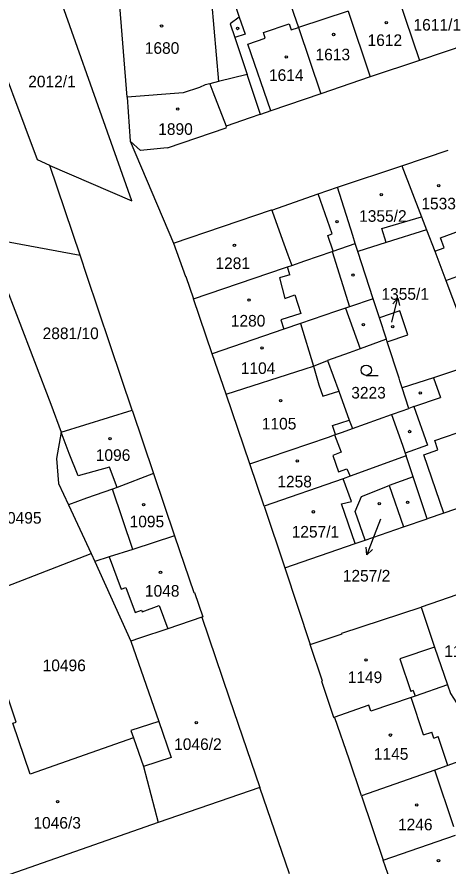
# Model space of a CAD drawing. Extents: x -564952 to -564307, y -1202373 to -1201847.
# Drawn here: x -564475.9 to -564412.8, y -1202215.7 to -1202091.3 of the extents above; entities that cross this region are included whole.
import ezdxf

# ---------------------------------------------------------------- set-up
doc = ezdxf.new("R2010")
doc.units = 0
for name, color, linetype in [('Hranice parcel', 7, 'Continuous'), ('Parcelní čísla', 7, 'Continuous'), ('Pop  PČ popisy', 7, 'Continuous'), ('Vnitřní kresba', 7, 'Continuous'), ('Značky budov', 7, 'Continuous'), ('Značky kultur', 7, 'Continuous')]:
    doc.layers.add(name, color=color, linetype=linetype)

msp = doc.modelspace()

# ---------------------------------------------------------------- linework, layer by layer
at = {"layer": 'Hranice parcel'}
for p, q in [((-564459.79, -1202103), (-564461.05, -1202087.35)), ((-564420.25, -1202088.03), (-564416.99, -1202097.64)), ((-564427.46, -1202090.41), (-564424.23, -1202100.06)), ((-564434.73, -1202092.8), (-564431.46, -1202102.52)), ((-564409.17, -1202094.97), (-564416.99, -1202097.64)), ((-564416.99, -1202097.64), (-564424.23, -1202100.06)), ((-564424.23, -1202100.06), (-564431.46, -1202102.52)), ((-564459.79, -1202103), (-564459.35, -1202109.45)), ((-564459.35, -1202109.45), (-564453, -1202124.38)), ((-564419.59, -1202113.07), (-564412.8, -1202110.76)), ((-564466.68, -1202126.15), (-564471.12, -1202112.99)), ((-564428.98, -1202116.19), (-564419.59, -1202113.07)), ((-564419.59, -1202113.07), (-564416.72, -1202120.54)), ((-564416.72, -1202120.54), (-564415.98, -1202122.44)), ((-564415.98, -1202122.44), (-564414.78, -1202125.53)), ((-564484.26, -1202122.87), (-564466.68, -1202126.15)), ((-564426.01, -1202125.59), (-564426.4, -1202124.41)), ((-564423.77, -1202132.5), (-564426.01, -1202125.59)), ((-564414.78, -1202125.53), (-564413.14, -1202129.85)), ((-564413.14, -1202129.85), (-564406.69, -1202127.47)), ((-564413.14, -1202129.85), (-564411.2, -1202134.99)), ((-564447.33, -1202140.55), (-564450.07, -1202132.51)), ((-564445.31, -1202146.49), (-564447.33, -1202140.55)), ((-564432.52, -1202142.36), (-564430.47, -1202141.57)), ((-564441.84, -1202156.68), (-564445.31, -1202146.49)), ((-564470.96, -1202147.96), (-564469.44, -1202152.01)), ((-564469.44, -1202152.01), (-564459.05, -1202148.8)), ((-564459.05, -1202148.8), (-564455.92, -1202158.1)), ((-564426.82, -1202151.52), (-564421.12, -1202149.47)), ((-564421.12, -1202149.47), (-564419.5, -1202153.95)), ((-564439.72, -1202162.87), (-564441.84, -1202156.68)), ((-564455.92, -1202158.1), (-564452.85, -1202167.22)), ((-564421.42, -1202159.82), (-564419.33, -1202165.89)), ((-564468.39, -1202162.66), (-564465.07, -1202169.78)), ((-564439.72, -1202162.87), (-564436.73, -1202171.88)), ((-564424.96, -1202167.83), (-564426.41, -1202163.62)), ((-564419.33, -1202165.89), (-564415.88, -1202164.71)), ((-564424.96, -1202167.83), (-564419.33, -1202165.89)), ((-564465.07, -1202169.78), (-564464.51, -1202170.97)), ((-564464.51, -1202170.97), (-564459.23, -1202182.61)), ((-564436.73, -1202171.88), (-564433, -1202183.12)), ((-564410.14, -1202175.34), (-564416.78, -1202177.62)), ((-564440.39, -1202204.01), (-564455.26, -1202209.13)), ((-564436.03, -1202216.65), (-564440.39, -1202204.01)), ((-564425.49, -1202205.25), (-564422.31, -1202214.68)), ((-564455.26, -1202209.13), (-564481.73, -1202218.41)), ((-564422.31, -1202214.68), (-564411.73, -1202210.99)), ((-564419.91, -1202221.63), (-564422.31, -1202214.68))]:
    msp.add_line(p, q, dxfattribs=at)
for points in [[(-564471.12, -1202112.99), (-564472.91, -1202112.19), (-564480.33, -1202092.49), (-564473.1, -1202078.61)], [(-564471.12, -1202112.99), (-564459.11, -1202118.17), (-564473.1, -1202078.61)], [(-564438.3, -1202082.34), (-564437.33, -1202085.18), (-564435.44, -1202090.73), (-564434.73, -1202092.8)], [(-564444.37, -1202088.37), (-564443.39, -1202091.32), (-564444.71, -1202092.27)], [(-564444.71, -1202092.27), (-564444.03, -1202094.3), (-564442.23, -1202099.7)], [(-564442.23, -1202099.7), (-564446.4, -1202100.73), (-564447.69, -1202101.05), (-564448.37, -1202101.22)], [(-564440.28, -1202105.54), (-564440.37, -1202105.26), (-564442.23, -1202099.7)], [(-564448.37, -1202101.22), (-564449.2, -1202101.6), (-564451.6, -1202102.39), (-564459.79, -1202103)], [(-564431.46, -1202102.52), (-564438.77, -1202105.01), (-564440.28, -1202105.54)], [(-564440.28, -1202105.54), (-564440.39, -1202105.56), (-564441.79, -1202106.04), (-564445.32, -1202107.24), (-564445.37, -1202107.57), (-564453.91, -1202110.48), (-564453.95, -1202110.41), (-564457.83, -1202110.82), (-564459.35, -1202109.45)], [(-564438.62, -1202119.56), (-564431.81, -1202117.18), (-564428.98, -1202116.19)], [(-564426.4, -1202124.41), (-564426.76, -1202123.25), (-564428.98, -1202116.19)], [(-564453, -1202124.38), (-564438.65, -1202119.52), (-564438.62, -1202119.56)], [(-564415.98, -1202122.44), (-564421.88, -1202124.29), (-564426.01, -1202125.59)], [(-564484.26, -1202122.87), (-564477.85, -1202129.99), (-564475.76, -1202135.44), (-564470.96, -1202147.96)], [(-564453, -1202124.38), (-564451.24, -1202129.27), (-564451.18, -1202129.25), (-564450.07, -1202132.51)], [(-564450.07, -1202132.51), (-564436.76, -1202128), (-564436.34, -1202127.85), (-564435.71, -1202127.63), (-564433.79, -1202126.97), (-564429.79, -1202125.58), (-564429.65, -1202125.53), (-564426.4, -1202124.41)], [(-564459.05, -1202148.8), (-564462.21, -1202139.4), (-564464.03, -1202134.02), (-564465.63, -1202129.27), (-564466.68, -1202126.15)], [(-564423.77, -1202132.5), (-564427.25, -1202133.68), (-564427.85, -1202133.89), (-564429.28, -1202134.37)], [(-564421.85, -1202138.41), (-564422.86, -1202135.31), (-564423.77, -1202132.5)], [(-564429.28, -1202134.37), (-564434.43, -1202136.12), (-564436.85, -1202136.95), (-564447.33, -1202140.55)], [(-564421.85, -1202138.41), (-564421.99, -1202138.46), (-564425.69, -1202139.82), (-564427.28, -1202140.4), (-564430.47, -1202141.57)], [(-564419.97, -1202144.14), (-564421.72, -1202138.83), (-564421.85, -1202138.41)], [(-564445.31, -1202146.49), (-564433.74, -1202142.77), (-564432.52, -1202142.36)], [(-564430.47, -1202141.57), (-564428.83, -1202146.03), (-564427.28, -1202150.27), (-564426.82, -1202151.52)], [(-564408.53, -1202141.96), (-564414.93, -1202144.06), (-564419.54, -1202145.57)], [(-564419.54, -1202145.57), (-564419.89, -1202144.52), (-564419.97, -1202144.14)], [(-564421.12, -1202149.47), (-564420.8, -1202149.35), (-564418.56, -1202148.56), (-564419.54, -1202145.57)], [(-564469.44, -1202152.01), (-564470.14, -1202155.87), (-564469.82, -1202159.55), (-564468.39, -1202162.66)], [(-564429.43, -1202152.44), (-564429.29, -1202152.39), (-564428.29, -1202152.02), (-564426.82, -1202151.52)], [(-564441.84, -1202156.68), (-564430.33, -1202152.75), (-564429.43, -1202152.44)], [(-564419.5, -1202153.95), (-564419.08, -1202155.11), (-564418.94, -1202155.51)], [(-564418.94, -1202155.51), (-564427.16, -1202158.47), (-564428.17, -1202158.84), (-564439.72, -1202162.87)], [(-564415.88, -1202164.71), (-564415.98, -1202164.41), (-564417.92, -1202158.58), (-564418.94, -1202155.51)], [(-564455.92, -1202158.1), (-564461.27, -1202160.11), (-564461.93, -1202160.36), (-564465.74, -1202161.69), (-564468.39, -1202162.66)], [(-564426.41, -1202163.62), (-564425.49, -1202161.44), (-564421.42, -1202159.82)], [(-564401.92, -1202159.96), (-564406.89, -1202161.65), (-564413.42, -1202163.87), (-564415.88, -1202164.71)], [(-564452.85, -1202167.22), (-564458.96, -1202169.19), (-564462.42, -1202170.3), (-564464.51, -1202170.97)], [(-564452.85, -1202167.22), (-564450.05, -1202175.52), (-564449.91, -1202175.48), (-564448.7, -1202179.07), (-564448.84, -1202179.12)], [(-564436.73, -1202171.88), (-564426.42, -1202168.33), (-564424.96, -1202167.83)], [(-564500.99, -1202168.69), (-564489.98, -1202179.46), (-564465.07, -1202169.78)], [(-564433, -1202183.12), (-564428.32, -1202181.55), (-564428.35, -1202181.47), (-564416.78, -1202177.62)], [(-564416.78, -1202177.62), (-564414.79, -1202183.49), (-564412.92, -1202189.01)], [(-564458.87, -1202196.74), (-564473.97, -1202202.06), (-564476.51, -1202194.63), (-564476.01, -1202194.45), (-564477.42, -1202190.36), (-564477.98, -1202190.57), (-564482.07, -1202179.28), (-564486.31, -1202180.92), (-564486.99, -1202179.15), (-564492.02, -1202181.09), (-564491.34, -1202182.86), (-564493.63, -1202183.74), (-564494.46, -1202184.06)], [(-564448.84, -1202179.12), (-564453.85, -1202180.8), (-564457.98, -1202182.19), (-564459.23, -1202182.61)], [(-564448.84, -1202179.12), (-564444.86, -1202190.93), (-564440.39, -1202204.01)], [(-564459.23, -1202182.61), (-564455.17, -1202194.39), (-564459.23, -1202195.69), (-564458.87, -1202196.74)], [(-564429.54, -1202193.79), (-564431.31, -1202188.54), (-564431.18, -1202188.49), (-564433, -1202183.12)], [(-564412.92, -1202189.01), (-564417.66, -1202190.65), (-564418.23, -1202190.85), (-564424.11, -1202192.88), (-564424.43, -1202191.99), (-564429.54, -1202193.79)], [(-564412.92, -1202189.01), (-564412.48, -1202190.3), (-564410.26, -1202193.68), (-564408.45, -1202199.22)], [(-564425.49, -1202205.25), (-564427.31, -1202199.89), (-564429.37, -1202193.82), (-564429.51, -1202193.87), (-564429.54, -1202193.79)], [(-564458.87, -1202196.74), (-564457.4, -1202200.98), (-564455.26, -1202209.13)], [(-564409.94, -1202199.76), (-564412.86, -1202200.81), (-564413, -1202200.86), (-564414.77, -1202201.48), (-564425.49, -1202205.25)]]:
    msp.add_lwpolyline(points, dxfattribs=at)
at = {"layer": 'Pop  PČ popisy'}
for p, q in [((-564420.92, -1202135.32), (-564420.19, -1202132.41)), ((-564420.19, -1202132.41), (-564420.92, -1202133.26)), ((-564420.19, -1202132.41), (-564419.95, -1202133.5)), ((-564421.07, -1202135.93), (-564420.92, -1202135.32)), ((-564422.73, -1202164.75), (-564423.65, -1202167.16)), ((-564423.65, -1202167.16), (-564424.72, -1202169.96)), ((-564424.72, -1202169.96), (-564424.83, -1202168.85)), ((-564424.72, -1202169.96), (-564423.9, -1202169.21))]:
    msp.add_line(p, q, dxfattribs=at)
at = {"layer": 'Vnitřní kresba'}
for p, q in [((-564447.42, -1202088.99), (-564446.4, -1202100.73)), ((-564443.39, -1202091.32), (-564442.51, -1202093.79)), ((-564427.46, -1202090.41), (-564434.73, -1202092.8)), ((-564439.85, -1202093.54), (-564436.09, -1202092.27)), ((-564436.09, -1202092.27), (-564435.8, -1202093.15)), ((-564442.51, -1202093.79), (-564444.03, -1202094.3)), ((-564439.57, -1202094.4), (-564439.85, -1202093.54)), ((-564435.8, -1202093.15), (-564434.73, -1202092.8)), ((-564442.13, -1202095.25), (-564439.57, -1202094.4)), ((-564438.77, -1202105.01), (-564442.13, -1202095.25)), ((-564447.69, -1202101.05), (-564447.25, -1202102.21)), ((-564447.25, -1202102.21), (-564445.32, -1202107.24)), ((-564429.76, -1202123.03), (-564431.81, -1202117.18)), ((-564438.62, -1202119.56), (-564438.51, -1202119.85)), ((-564438.51, -1202119.85), (-564436.85, -1202124.46)), ((-564422.52, -1202122.22), (-564416.72, -1202120.54)), ((-564421.88, -1202124.29), (-564422.52, -1202122.22)), ((-564413.93, -1202123.58), (-564411.16, -1202122.55)), ((-564430.44, -1202123.27), (-564429.76, -1202123.03)), ((-564429.65, -1202125.53), (-564430.44, -1202123.27)), ((-564413.38, -1202125.07), (-564413.93, -1202123.58)), ((-564436.85, -1202124.46), (-564436.26, -1202126.1)), ((-564436.26, -1202126.1), (-564435.71, -1202127.63)), ((-564429.79, -1202125.58), (-564427.25, -1202133.68)), ((-564414.78, -1202125.53), (-564413.38, -1202125.07)), ((-564435.96, -1202129), (-564436.34, -1202127.85)), ((-564435.96, -1202129), (-564437.49, -1202129.47)), ((-564437.49, -1202129.47), (-564436.73, -1202132.45)), ((-564436.73, -1202132.45), (-564435.27, -1202131.92)), ((-564435.27, -1202131.92), (-564434.38, -1202134.65)), ((-564434.38, -1202134.65), (-564437.29, -1202135.61)), ((-564427.85, -1202133.89), (-564425.69, -1202139.82)), ((-564419.89, -1202134.29), (-564422.86, -1202135.31)), ((-564418.69, -1202137.79), (-564419.89, -1202134.29)), ((-564437.29, -1202135.61), (-564436.85, -1202136.95)), ((-564434.43, -1202136.12), (-564432.52, -1202142.36)), ((-564421.72, -1202138.83), (-564418.69, -1202137.79)), ((-564432.52, -1202142.36), (-564431.72, -1202145.12)), ((-564414.93, -1202144.06), (-564413.93, -1202146.97)), ((-564431.72, -1202145.12), (-564431.13, -1202146.78)), ((-564431.13, -1202146.78), (-564428.83, -1202146.03)), ((-564417.81, -1202148.3), (-564413.93, -1202146.97)), ((-564417.81, -1202148.3), (-564418.56, -1202148.56)), ((-564417.81, -1202148.3), (-564415.81, -1202153.93)), ((-564429.73, -1202151.07), (-564427.28, -1202150.27)), ((-564429.29, -1202152.39), (-564429.73, -1202151.07)), ((-564414.78, -1202153.23), (-564405.48, -1202150.04)), ((-564468.27, -1202155.14), (-564469.44, -1202152.01)), ((-564429.43, -1202152.44), (-564428.45, -1202154.94)), ((-564414.3, -1202154.63), (-564414.78, -1202153.23)), ((-564415.81, -1202153.93), (-564419.08, -1202155.11)), ((-564416.35, -1202155.33), (-564414.3, -1202154.63)), ((-564466.98, -1202158.44), (-564468.27, -1202155.14)), ((-564428.45, -1202154.94), (-564429.7, -1202155.43)), ((-564429.7, -1202155.43), (-564428.88, -1202157.86)), ((-564413.42, -1202163.87), (-564416.35, -1202155.33)), ((-564462.37, -1202157.16), (-564466.98, -1202158.44)), ((-564461.27, -1202160.11), (-564462.37, -1202157.16)), ((-564428.88, -1202157.86), (-564427.66, -1202157.39)), ((-564427.66, -1202157.39), (-564427.16, -1202158.47)), ((-564417.92, -1202158.58), (-564421.42, -1202159.82)), ((-564426.96, -1202162.19), (-564428.17, -1202158.84)), ((-564458.96, -1202169.19), (-564461.93, -1202160.36)), ((-564428.43, -1202162.5), (-564426.96, -1202162.19)), ((-564426.42, -1202168.33), (-564428.43, -1202162.5)), ((-564462.42, -1202170.3), (-564460.65, -1202175.03)), ((-564460.65, -1202175.03), (-564459.97, -1202174.78)), ((-564459.97, -1202174.78), (-564458.62, -1202178.41)), ((-564458.62, -1202178.41), (-564457.68, -1202178.06)), ((-564457.68, -1202178.06), (-564457.58, -1202178.34)), ((-564457.58, -1202178.34), (-564455.1, -1202177.42)), ((-564455.1, -1202177.42), (-564453.85, -1202180.8)), ((-564414.79, -1202183.49), (-564419.87, -1202185.18)), ((-564419.87, -1202185.18), (-564418.25, -1202189.96)), ((-564417.93, -1202189.86), (-564418.25, -1202189.96)), ((-564416.41, -1202196.33), (-564418.23, -1202190.85)), ((-564417.93, -1202189.86), (-564417.66, -1202190.65)), ((-564455.17, -1202194.39), (-564453.36, -1202199.65)), ((-564416.41, -1202196.33), (-564415.18, -1202195.92)), ((-564414.89, -1202196.79), (-564415.18, -1202195.92)), ((-564414.89, -1202196.79), (-564414.26, -1202196.59)), ((-564412.86, -1202200.81), (-564414.26, -1202196.59)), ((-564453.36, -1202199.65), (-564457.4, -1202200.98)), ((-564411.97, -1202209.79), (-564414.77, -1202201.48))]:
    msp.add_line(p, q, dxfattribs=at)
at = {"layer": 'Značky budov'}
for centre in [(-564454.76, -1202092.6), (-564421.86, -1202092.11), (-564443.62, -1202092.96), (-564429.57, -1202093.84), (-564436.51, -1202097.12), (-564452.38, -1202104.75), (-564414.19, -1202115.95), (-564422.6, -1202117.26), (-564429.06, -1202121.21), (-564444.08, -1202124.71), (-564426.75, -1202129.05), (-564441.95, -1202132.71), (-564425.22, -1202136.3), (-564420.91, -1202136.61), (-564440.05, -1202139.71), (-564416.89, -1202146.3), (-564437.33, -1202147.41), (-564418.45, -1202151.94), (-564462.28, -1202152.98), (-564434.9, -1202156.25), (-564422.89, -1202162.5), (-564418.75, -1202162.32), (-564457.38, -1202162.63), (-564432.54, -1202163.69), (-564454.91, -1202172.54), (-564424.83, -1202185.37), (-564449.67, -1202194.54), (-564421.25, -1202196.37), (-564469.96, -1202206.12), (-564417.4, -1202206.59), (-564414.22, -1202214.73)]:
    msp.add_circle(centre, 0.175, dxfattribs=at)
at = {"layer": 'Značky kultur'}
msp.add_line((-564424.79, -1202143.72), (-564423.04, -1202143.72), dxfattribs=at)
msp.add_circle((-564424.79, -1202142.97), 0.75, dxfattribs=at)

# ---------------------------------------------------------------- texts
at = {"layer": 'Parcelní čísla'}
for s, p in [('1611/1', (-564417.88, -1202093.27)), ('1612', (-564424.6, -1202095.52)), ('1680', (-564457.21, -1202096.67)), ('1613', (-564432.22, -1202097.62)), ('1614', (-564439.03, -1202100.63)), ('2012/1', (-564474.27, -1202101.57)), ('1890', (-564455.24, -1202108.53)), ('1533', (-564416.73, -1202119.43)), ('1355/2', (-564425.84, -1202121.25)), ('1281', (-564446.87, -1202128.17)), ('1355/1', (-564422.57, -1202132.66)), ('1280', (-564444.62, -1202136.58)), ('2881/10', (-564472.16, -1202138.42)), ('1104', (-564443.16, -1202143.52)), ('3223', (-564426.99, -1202147.11)), ('1105', (-564440.08, -1202151.64)), ('1096', (-564464.38, -1202156.24)), ('1258', (-564437.81, -1202160.12)), ('10495', (-564478.64, -1202165.42)), ('1095', (-564459.43, -1202165.96)), ('1257/1', (-564435.71, -1202167.46)), ('1257/2', (-564428.23, -1202173.89)), ('1048', (-564457.19, -1202176.11)), ('1147', (-564413.37, -1202184.92)), ('10496', (-564472.16, -1202187.01)), ('1149', (-564427.51, -1202188.75)), ('1046/2', (-564452.91, -1202198.54)), ('1145', (-564423.68, -1202199.97)), ('1046/3', (-564473.51, -1202210.05)), ('1246', (-564420.15, -1202210.3))]:
    msp.add_text(s, height=1.7, dxfattribs=at).set_placement(p)

doc.saveas('drawing.dxf')
